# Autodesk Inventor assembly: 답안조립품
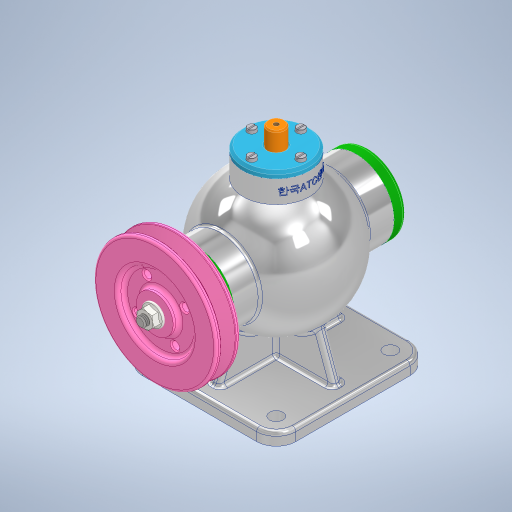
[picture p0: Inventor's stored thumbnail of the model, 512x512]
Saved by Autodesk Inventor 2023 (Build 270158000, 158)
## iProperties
Created: 2023-07
Part Number: 답안조립품
Document SubType Name: Assembly
Designer: Owner
Author: Owner
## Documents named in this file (16)
- C:\Users\Owner\Desktop\730711V1004\답안조립품.iam
- C:\Users\Owner\Desktop\730711V1004\본체.ipt
- C:\Users\Owner\Desktop\730711V1004\뒤커버.ipt
- C:\Users\Owner\Desktop\730711V1004\앞커버.ipt
- C:\Users\Owner\Desktop\730711V1004\상부커버.ipt
- C:\Users\Owner\Desktop\730711V1004\베어링- 6202.ipt
- KS B 2023 - 6202 - 15 x 35 x 11 - 7.8.ipt
- C:\Users\Owner\Desktop\730711V1004\칼라.ipt
- C:\Users\Owner\Desktop\730711V1004\편심축.ipt
- C:\Users\Owner\Desktop\730711V1004\키 4 x 4 x 12.ipt
- C:\Users\Owner\Desktop\730711V1004\오일실 15 30 7.ipt
- C:\Users\Owner\Desktop\730711V1004\V-벨트풀리.ipt
- C:\Users\Owner\Desktop\730711V1004\너트 M8.ipt
- C:\Users\Owner\Desktop\730711V1004\볼트 M4 x 16.ipt
- C:\Users\Owner\Desktop\730711V1004\슬라이드.ipt
- C:\Users\Owner\Desktop\730711V1004\볼트 M4 x 12.ipt
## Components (15 placed, 4 different names)
1. KS B 2023 - 6202 - 15 x 35 x 11 - 7.8:1
2. KS B 2023 - 6202 - 15 x 35 x 11 - 7.8:2
3. V-벨트풀리:1
4. ISO 4762 M4 x 16:1
5. ISO 4762 M4 x 16:2
6. ISO 4762 M4 x 16:3
7. ISO 4762 M4 x 16:4
8. ISO 4762 M4 x 16:5
9. ISO 4762 M4 x 16:6
10. ISO 4762 M4 x 16:7
11. ISO 4762 M4 x 16:8
12. KS B 1021 - 에 따름 ISO 1207 - 미터 A  M 4 x 12:1
13. KS B 1021 - 에 따름 ISO 1207 - 미터 A  M 4 x 12:2
14. KS B 1021 - 에 따름 ISO 1207 - 미터 A  M 4 x 12:3
15. KS B 1021 - 에 따름 ISO 1207 - 미터 A  M 4 x 12:4
